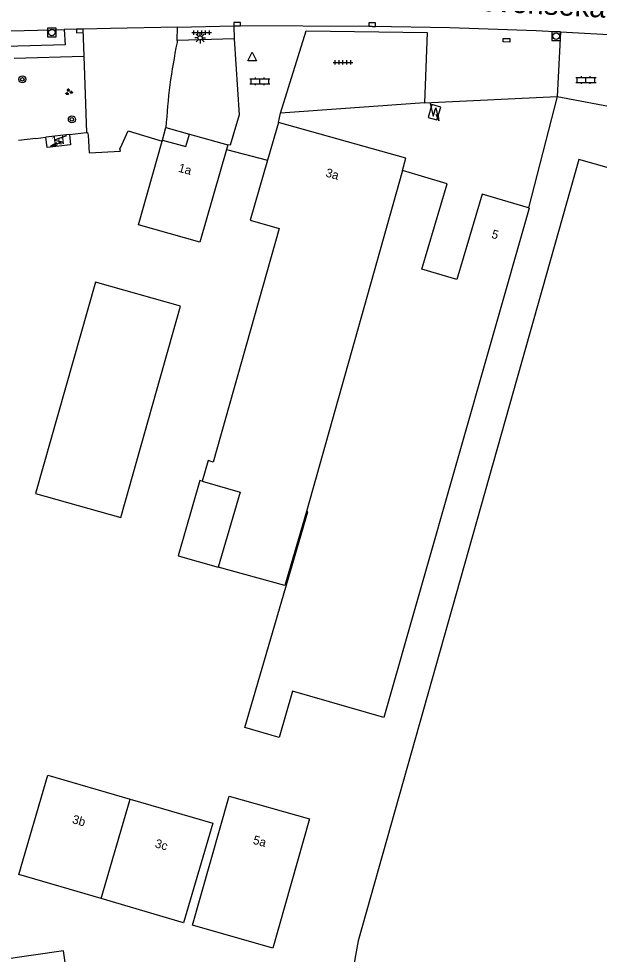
# Model space of a CAD drawing. Extents: x 132999 to 136000, y 398499 to 400501.
# Drawn here: x 134078.2 to 134144.6, y 398799.5 to 398906.5 of the extents above; entities that cross this region are included whole.
import ezdxf

# ---------------------------------------------------------------- set-up
doc = ezdxf.new("R2010")
doc.units = 0
for name, color, linetype in [('gg-afsc-hekwerk', 7, 'Continuous'), ('gg-afsc-muur', 7, 'Continuous'), ('gg-anno-huisnummerreeks BGT', 7, 'Continuous'), ('gg-anno-openbare ruimte label', 7, 'Continuous'), ('gg-bbg-bijgebouw', 7, 'Continuous'), ('gg-bbg-gedigitaliseerde bebouwing', 7, 'Continuous'), ('gg-bbg-hoofdgebouw', 7, 'Continuous'), ('gg-bbg-lage trafo', 7, 'Continuous'), ('gg-bbg-luifel en loopbrug', 7, 'Continuous'), ('gg-bbg-onder overbouw', 7, 'Continuous'), ('gg-bbg-pand overbouw', 7, 'Continuous'), ('gg-bbg-tussenscheiding', 7, 'Continuous'), ('gg-knt-verharding', 7, 'Continuous'), ('gg-knt-verharding nz', 7, 'Continuous'), ('gt-grn-vlakafsluiter', 7, 'Continuous'), ('gt-grn-weggrens', 7, 'Continuous'), ('gt-symb-boom', 7, 'Continuous'), ('gt-symb-groenvak', 7, 'Continuous'), ('gt-symb-klinker verharding', 7, 'Continuous'), ('gt-symb-kolk', 7, 'Continuous'), ('gt-symb-kolk center center', 7, 'Continuous'), ('gt-symb-lichtmast', 7, 'Continuous'), ('gt-symb-rioolschacht', 7, 'Continuous'), ('gt-symb-tegel verharding', 7, 'Continuous'), ('gt-symb-trafo symbool', 7, 'Continuous'), ('gt-symb-waterafsluiter', 7, 'Continuous')]:
    doc.layers.add(name, color=color, linetype=linetype)

# ---------------------------------------------------------------- blocks, each defined once
blk = doc.blocks.new('gt0-RS')
at = {"layer": 'gt-symb-rioolschacht'}
blk.add_lwpolyline([(-0.5, -0.5), (0.5, -0.5), (0.5, 0.5), (-0.5, 0.5)], close=True, dxfattribs=at)
blk.add_circle((0, 0), 0.375, dxfattribs=at)
blk = doc.blocks.new('gt0-KOLK')
at = {"layer": 'gt-symb-kolk'}
blk.add_lwpolyline([(0, 0), (0.37, 0), (0.37, 0.4), (-0.38, 0.4), (-0.38, 0), (0, 0)], dxfattribs=at)
blk = doc.blocks.new('gt0-KOLKCC')
at = {"layer": 'gt-symb-kolk center center'}
blk.add_lwpolyline([(-0.38, 0.2), (0.38, 0.2), (0.38, -0.2), (-0.38, -0.2)], close=True, dxfattribs=at)
blk = doc.blocks.new('gt0-LMAST')
at = {"layer": 'gt-symb-lichtmast'}
for p, q in [((-0.18, 0.17), (-0.45, 0.44)), ((-0.01, 0.25), (-0.01, 0.62)), ((0.17, 0.17), (0.44, 0.44)), ((-0.26, 0), (-0.63, 0)), ((-0.18, -0.18), (-0.45, -0.45)), ((-0.01, -0.25), (-0.01, -0.63)), ((0.44, -0.45), (0.17, -0.18)), ((0.24, 0), (0.62, 0))]:
    blk.add_line(p, q, dxfattribs=at)
blk.add_circle((-0.01, 0), 0.25, dxfattribs=at)
blk = doc.blocks.new('gt0-TEG1')
at = {"layer": 'gt-symb-tegel verharding'}
for p, q in [((-1.12, 0), (1.12, 0)), ((-0.9, -0.25), (-0.9, 0.25)), ((-0.45, -0.25), (-0.45, 0.25)), ((0, -0.25), (0, 0.25)), ((0.45, -0.25), (0.45, 0.25)), ((0.9, -0.25), (0.9, 0.25))]:
    blk.add_line(p, q, dxfattribs=at)
blk = doc.blocks.new('gt0-WAFSL')
at = {"layer": 'gt-symb-waterafsluiter'}
for p, q in [((-0.5, -0.33), (0, 0.67)), ((0, 0.67), (0.5, -0.33)), ((0.5, -0.33), (-0.5, -0.33))]:
    blk.add_line(p, q, dxfattribs=at)
blk = doc.blocks.new('gt0-KL1')
at = {"layer": 'gt-symb-klinker verharding'}
for p, q in [((-1.15, 0.3), (1.15, 0.3)), ((-1, -0.3), (-1, 0.3)), ((-0.5, 0.3), (-0.5, 0.45)), ((0, -0.3), (0, 0.3)), ((0.5, 0.3), (0.5, 0.45)), ((1, -0.3), (1, 0.3)), ((-1.15, -0.3), (1.15, -0.3)), ((-0.5, -0.45), (-0.5, -0.3)), ((0.5, -0.45), (0.5, -0.3))]:
    blk.add_line(p, q, dxfattribs=at)
blk = doc.blocks.new('gt0-HSP')
at = {"layer": 'gt-symb-trafo symbool'}
for points in [[(0.77, 0.75), (-0.53, 0), (0.47, 0), (-0.83, -0.75)], [(-0.22, -0.24), (-0.83, -0.75), (-0.08, -0.48)]]:
    blk.add_lwpolyline(points, dxfattribs=at)
blk = doc.blocks.new('gt0-BOOM')
at = {"layer": 'gt-symb-boom'}
for radius in [0.4, 0.2]:
    blk.add_circle((0, 0), radius, dxfattribs=at)
blk = doc.blocks.new('gt0-GRVAK')
at = {"layer": 'gt-symb-groenvak'}
for p, q in [((-0.11, 0.19), (-0.23, 0.24)), ((-0.18, 0.15), (0.09, 0.15)), ((-0.09, 0.21), (-0.16, 0.32)), ((-0.05, 0.21), (-0.05, 0.39)), ((0, 0.21), (0.06, 0.32)), ((0.01, 0.19), (0.13, 0.24)), ((0.26, -0.05), (0.2, 0.06)), ((0.3, -0.05), (0.3, 0.13)), ((0.35, -0.05), (0.41, 0.06)), ((-0.24, -0.23), (-0.36, -0.18)), ((-0.32, -0.26), (-0.05, -0.26)), ((-0.23, -0.21), (-0.29, -0.09)), ((-0.18, -0.2), (-0.18, -0.02)), ((-0.14, -0.21), (-0.07, -0.09)), ((-0.12, -0.23), (0, -0.18)), ((0.24, -0.07), (0.12, -0.02)), ((0.17, -0.11), (0.44, -0.11)), ((0.37, -0.07), (0.49, -0.02))]:
    blk.add_line(p, q, dxfattribs=at)

msp = doc.modelspace()

# ---------------------------------------------------------------- linework, layer by layer
at = {"layer": 'gg-afsc-hekwerk'}
msp.add_line((134102, 398891.51), (134106.7, 398890.29), dxfattribs=at)
msp.add_lwpolyline([(134086.18, 398893.13), (134086.3, 398891.1), (134089.89, 398891.3), (134089.8, 398891.58), (134089.88, 398891.67), (134090.73, 398893.62), (134094.64, 398892.45)], dxfattribs=at)
at = {"layer": 'gg-afsc-muur'}
for p, q in [((134084.02, 398893.22), (134085.98, 398893.45)), ((134080.19, 398892.77), (134078.22, 398892.53))]:
    msp.add_line(p, q, dxfattribs=at)
msp.add_lwpolyline([(134085.98, 398893.45), (134086.11, 398893.46), (134086.18, 398893.13)], dxfattribs=at)
at = {"layer": 'gg-bbg-bijgebouw'}
msp.add_lwpolyline([(134080.16, 398852.16), (134089.9, 398849.43), (134096.75, 398873.58), (134087.03, 398876.34), (134080.16, 398852.16)], dxfattribs=at)
at = {"layer": 'gg-bbg-gedigitaliseerde bebouwing'}
for p, q in [((134142.31, 398890.37), (134117.04, 398800.99)), ((134117.04, 398800.99), (134116.3, 398796.94))]:
    msp.add_line(p, q, dxfattribs=at)
msp.add_lwpolyline([(134098.99, 398792.28), (134084.73, 398790.32), (134083.34, 398799.87), (134058.49, 398796.26), (134057.92, 398800.21)], dxfattribs=at)
at = {"layer": 'gg-bbg-hoofdgebouw'}
for p, q in [((134107.94, 398894.59), (134106.7, 398890.29)), ((134084.02, 398893.22), (134081.34, 398892.9)), ((134097.76, 398893.25), (134102.15, 398892.04)), ((134094.68, 398892.57), (134094.64, 398892.45)), ((134102.15, 398892.04), (134102, 398891.51)), ((134102, 398891.51), (134098.93, 398880.9)), ((134136.62, 398884.8), (134136.53, 398884.83))]:
    msp.add_line(p, q, dxfattribs=at)
for points in [[(134147.7, 398896.09), (134145.8, 398889.36), (134142.31, 398890.37)], [(134122.11, 398889.1), (134122.52, 398890.49), (134107.94, 398894.59)], [(134084.02, 398893.22), (134084.16, 398892.05), (134081.48, 398891.74), (134081.34, 398892.9)], [(134098.93, 398880.9), (134091.93, 398882.89), (134094.64, 398892.45)], [(134106.7, 398890.29), (134104.7, 398883.4), (134108.02, 398882.47), (134100.48, 398855.76), (134099.91, 398855.92), (134099.22, 398853.58)], [(134136.53, 398884.83), (134131.23, 398886.4), (134128.33, 398876.62), (134124.34, 398877.8), (134127.24, 398887.58), (134122.11, 398889.1)], [(134136.62, 398884.8), (134119.99, 398826.56), (134109.55, 398829.57), (134108.02, 398824.26), (134104.09, 398825.39), (134111.3, 398850.05), (134111.14, 398850.09)], [(134099.22, 398853.58), (134103.55, 398852.31), (134101.04, 398843.73)], [(134111.14, 398850.09), (134108.67, 398841.63), (134101.04, 398843.73)], [(134087.66, 398805.83), (134078.24, 398808.59), (134081.57, 398819.96), (134090.99, 398817.21)], [(134090.99, 398817.21), (134100.42, 398814.45), (134097.09, 398803.07), (134087.66, 398805.83)], [(134098.12, 398802.78), (134102.32, 398817.53), (134111.5, 398814.97), (134107.28, 398800.17), (134098.12, 398802.78)]]:
    msp.add_lwpolyline(points, dxfattribs=at)
at = {"layer": 'gg-bbg-lage trafo'}
msp.add_lwpolyline([(134125.06, 398895.17), (134126.07, 398894.88), (134126.5, 398896.35), (134125.5, 398896.65), (134125.06, 398895.17)], dxfattribs=at)
at = {"layer": 'gg-bbg-luifel en loopbrug'}
msp.add_lwpolyline([(134099.22, 398853.58), (134098.93, 398853.66), (134096.47, 398845.02), (134101.04, 398843.73)], dxfattribs=at)
at = {"layer": 'gg-bbg-onder overbouw'}
msp.add_lwpolyline([(134094.68, 398892.57), (134097.33, 398891.83), (134097.76, 398893.25)], dxfattribs=at)
at = {"layer": 'gg-bbg-pand overbouw'}
for p, q in [((134094.68, 398892.57), (134095.07, 398894)), ((134095.07, 398894), (134097.76, 398893.25))]:
    msp.add_line(p, q, dxfattribs=at)
at = {"layer": 'gg-bbg-tussenscheiding'}
for p, q in [((134122.11, 398889.1), (134111.14, 398850.09)), ((134087.66, 398805.83), (134090.99, 398817.21))]:
    msp.add_line(p, q, dxfattribs=at)
at = {"layer": 'gg-knt-verharding'}
for p, q in [((134085.57, 398905.27), (134083.44, 398905.21)), ((134085.57, 398905.27), (134085.67, 398902.16)), ((134096.35, 398903.98), (134096.4, 398905.47)), ((134096.4, 398905.47), (134102.84, 398905.64)), ((134102.84, 398905.64), (134102.86, 398904.14)), ((134149.93, 398904.39), (134140.21, 398904.91)), ((134096.35, 398903.98), (134096.34, 398903.73)), ((134102.86, 398904.14), (134096.35, 398903.98)), ((134077.7, 398901.96), (134085.67, 398902.16)), ((134085.67, 398902.16), (134085.98, 398893.45)), ((134124.66, 398896.84), (134139.82, 398897.54)), ((134139.82, 398897.54), (134136.53, 398884.83)), ((134124.66, 398896.84), (134108.17, 398895.67)), ((134107.94, 398894.59), (134108.17, 398895.67)), ((134080.19, 398892.77), (134081.34, 398892.9))]:
    msp.add_line(p, q, dxfattribs=at)
for points in [[(134083.44, 398905.21), (134083.54, 398903.45), (134065.92, 398902.98)], [(134096.4, 398905.47), (134088.74, 398905.35), (134085.57, 398905.27)], [(134140.21, 398904.91), (134137.42, 398905.06), (134127.54, 398905.42), (134118.66, 398905.58), (134102.84, 398905.64)], [(134108.17, 398895.67), (134111.12, 398905.07), (134124.94, 398904.86), (134124.66, 398896.84)], [(134102.86, 398904.14), (134103.44, 398895.47), (134102.42, 398892.01), (134102.15, 398892.04)]]:
    msp.add_lwpolyline(points, dxfattribs=at)
msp.add_arc((134161.64, 398890.29), 66.67, 168.3731, 176.8134, dxfattribs=at)
at = {"layer": 'gg-knt-verharding nz'}
msp.add_line((134065.85, 398904.76), (134083.44, 398905.21), dxfattribs=at)
at = {"layer": 'gt-grn-vlakafsluiter'}
msp.add_line((134139.82, 398897.54), (134147.7, 398896.09), dxfattribs=at)
at = {"layer": 'gt-grn-weggrens'}
msp.add_line((134140.21, 398904.91), (134139.82, 398897.54), dxfattribs=at)

# ---------------------------------------------------------------- block references
at = {"layer": 'gt-symb-boom', "rotation": -88.73969615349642}
for p in [(134078.65, 398899.52), (134084.31, 398894.94)]:
    msp.add_blockref('gt0-BOOM', p, dxfattribs=at)
at = {"layer": 'gt-symb-groenvak'}
msp.add_blockref('gt0-GRVAK', (134083.96, 398898.07), dxfattribs=at)
at = {"layer": 'gt-symb-klinker verharding'}
for p in [(134105.82, 398899.29), (134143.11, 398899.45)]:
    msp.add_blockref('gt0-KL1', p, dxfattribs=at)
at = {"layer": 'gt-symb-kolk'}
for p, rotation in [((134103.21, 398905.63), -0.1718868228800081), ((134118.66, 398905.58), -1.0312126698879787), ((134085.21, 398905.26), -178.4989325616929)]:
    msp.add_blockref('gt0-KOLK', p, dxfattribs=dict(at, rotation=rotation))
at = {"layer": 'gt-symb-kolk center center', "rotation": -1.9492541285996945}
msp.add_blockref('gt0-KOLKCC', (134134.02, 398903.99), dxfattribs=at)
at = {"layer": 'gt-symb-lichtmast'}
msp.add_blockref('gt0-LMAST', (134098.99, 398904.25), dxfattribs=at)
at = {"layer": 'gt-symb-rioolschacht'}
for p in [(134082.02, 398904.89), (134139.71, 398904.47)]:
    msp.add_blockref('gt0-RS', p, dxfattribs=at)
at = {"layer": 'gt-symb-tegel verharding'}
for p in [(134099.16, 398904.86), (134115.32, 398901.46)]:
    msp.add_blockref('gt0-TEG1', p, dxfattribs=at)
at = {"layer": 'gt-symb-trafo symbool'}
for p, rotation in [((134125.79, 398895.8), 73.50377577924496), ((134082.8, 398892.46), -9.792146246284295)]:
    msp.add_blockref('gt0-HSP', p, dxfattribs=dict(at, rotation=rotation))
at = {"layer": 'gt-symb-waterafsluiter'}
msp.add_blockref('gt0-WAFSL', (134104.93, 398901.95), dxfattribs=at)

# ---------------------------------------------------------------- texts
at = {"layer": 'gg-anno-huisnummerreeks BGT'}
for s, rotation, p in [('1d', 6.7, (134082.02, 398891.97)), ('1a', 344.4, (134096.41, 398888.97)), ('3a', 344.3, (134113.26, 398888.42)), ('5', 343.4, (134132.23, 398881.41)), ('3b', 343.7, (134084.27, 398814.48)), ('3c', 343.7, (134093.74, 398811.72)), ('5a', 344.4, (134104.95, 398812.12))]:
    msp.add_text(s, height=1, rotation=rotation, dxfattribs=at).set_placement(p)
at = {"layer": 'gg-anno-openbare ruimte label'}
msp.add_text('Lovensekanaaldijk', height=2.5, rotation=356.8, dxfattribs=at).set_placement((134129.16, 398907.46))

doc.saveas('drawing.dxf')
